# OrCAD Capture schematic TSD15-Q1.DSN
size A; title: TSDxx-Q1 Unidirectional Protection Diodes in SOD-323; rev: 1.0; note: Datasheet: SLVSHX1
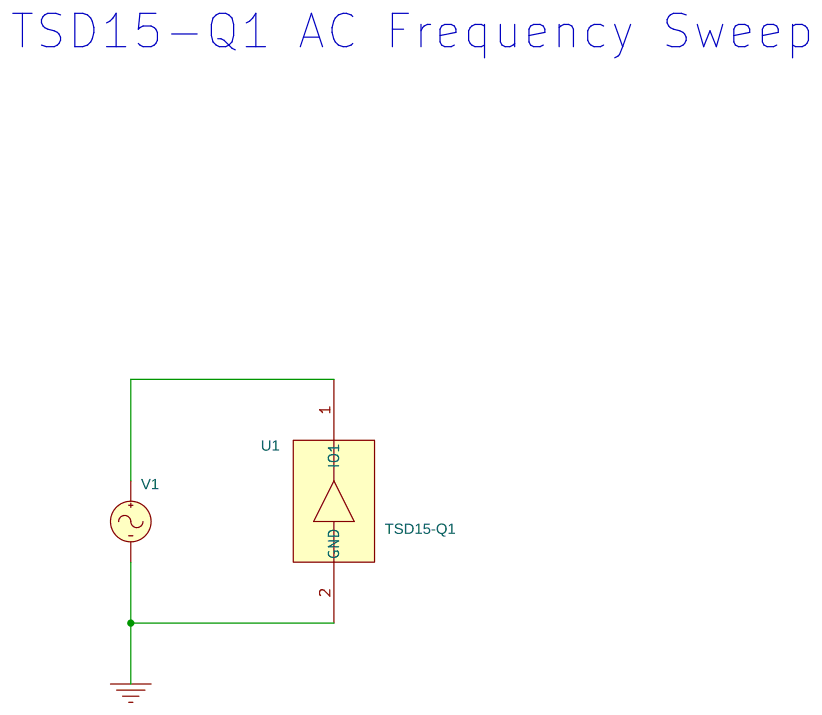
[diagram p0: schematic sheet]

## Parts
U1  TSD15-Q1
V1  VAC

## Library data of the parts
U1 = TSD15-Q1
V1 = VAC

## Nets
0: U1.2(GND) V1.2(-)
N02980: U1.1(IO1) V1.1(+)

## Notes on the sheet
- TSD15-Q1 AC Frequency Sweep
